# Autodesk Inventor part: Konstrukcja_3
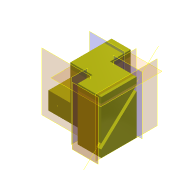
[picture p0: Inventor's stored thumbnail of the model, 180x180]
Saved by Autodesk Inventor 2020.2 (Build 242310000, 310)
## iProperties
Created: 2014-07
Part Number: Konstrukcja_3
Material: Ogólny
Document SubType Name: Modeling
Designer: F.Stasiak
Density: 1 g/cm^3
Appearance: Żółta
Catalog Web Link: www.expertbooks.pl
Manager: www.cadconsulting.pl
Company: Fabian Stasiak CAD Consulting
Author: F.Stasiak
Subject: Zbiór ćwiczeń. Autodesk Inventor 2020. Kurs Professional
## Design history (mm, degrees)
sketch "Szkic1"
  geometry: L1 (0, 0)-(1500, 0); L2 (1500, 0)-(1500, -500); L3 (1500, -500)-(2300, -500); L4 (2300, -500)-(2300, 700); L5 (2300, 700)-(1400, 700); L6 (1400, 700)-(1400, 1400); L7 (1400, 1400)-(300, 1400); L8 (300, 1400)-(300, 1100); L9 (300, 1100)-(0, 1100); L10 (0, 1100)-(0, 0)
  constraints: 20 end point, 9 perpendicular, 1 horizontal
  dimensions: "d0" = 1500 distance of L1.start L1.end; "d1" = 500 distance of L1.end L2.end; "d2" = 800 distance of L2.end L3.end; "d3" = 1200 distance of L3.end L4.end; "d4" = 900 distance of L4.end L5.end; "d5" = 700 distance of L5.end L6.end; "d6" = 1100 distance of L6.end L7.end; "d7" = 300 distance of L7.end L8.end
extrude "Wyciągnięcie proste1" new body sketch "Szkic1" distance "d8" = 1800; taper "d9" = 0 deg
sketch "Szkic2"
  geometry: L1 (0, 0)-(-1800, 0) reference; L2 (0, 1200)-(-1800, 1200) reference; L3 (-250, 0)-(-1369.018, 1200); L4 (-430, 0)-(-1549.018, 1200); L5 (0, 0)-(0, 1200) reference; 1 further point
  constraints: 4 end point, 4 point on line, 1 parallel
  dimensions: "d10" = 250 distance of L3.start L1.start; "d11" = 180 distance of L4.start L3.start; "d31" = 43 deg angle of L3 L5
extrude "Wyciągnięcie proste2" cut sketch "Szkic2" distance "d12" = 180 (= d11); taper "d13" = 0 deg
sketch "Szkic3"
  geometry: L1 (0, 0)-(1500, 0) reference; L2 (0, 0)-(0, 1800) reference; 1 further point
  dimensions: "d14" = 300 distance from line of point (300, 300) L1; "d15" = 300 distance from line of L2 point (300, 300)
hole "Otwór1" sketch "Szkic3" at (300, 300) diameter "d16" = 50; stored, may be unused: countersink angle "d20" = 90 deg, drill point angle "d22" = 118 deg; dims "d17" = 6, "d18" = 4, "d19" = 2, "d21" = 100
node "Płaszczyzna konstrukcyjna5"
node "Płaszczyzna konstrukcyjna3"
node "Płaszczyzna konstrukcyjna7"
node "Płaszczyzna konstrukcyjna11"
node "Oś konstrukcyjna2"
node "Płaszczyzna konstrukcyjna12"
node "Płaszczyzna konstrukcyjna13"
node "Płaszczyzna konstrukcyjna14"
sketch "Szkic5"
  geometry: L1 (0, 700)-(-1800, 700) reference; L2 (-1800, 0)-(-1800, 700) reference; 2 further points
  dimensions: "d60" = 250 distance from line of L1 point (-1600, 450); "d61" = 200 distance from line of L2 point (-1600, 450)
sketch "Szkic6"
  geometry: L1 (0, 0)-(0, 1800) reference; L2 (0, 1800)-(1500, 1800) reference; L3 (0, 600)-(750, 600); L4 (750, 600)-(750, 1800)
  constraints: 4 end point, 1 horizontal, 1 midpoint, 1 point on line
  dimensions: "d56" = 600 distance of L3.start L1.start
extrude "Wyciągnięcie proste3" cut sketch "Szkic6" extent not by distance; stored distance "d57" = 10; taper "d58" = 0 deg
hole "Otwór5" sketch "Szkic5" diameter "d62" = 50; stored, may be unused: countersink angle "d66" = 90 deg, drill point angle "d68" = 118 deg; dims "d63" = 6, "d64" = 4, "d65" = 2, "d67" = 100
node "Płaszczyzna konstrukcyjna18"
node "Płaszczyzna konstrukcyjna19"
node "Oś konstrukcyjna8"
node "Płaszczyzna konstrukcyjna21"
node "Bryła1"
